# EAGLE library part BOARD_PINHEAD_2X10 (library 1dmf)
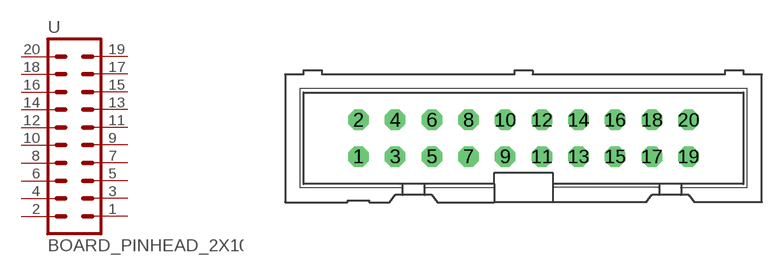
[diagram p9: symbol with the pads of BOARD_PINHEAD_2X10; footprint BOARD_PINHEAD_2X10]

Designator prefix -

## BOARD_PINHEAD_2X10  [BOARD_PINHEAD_2X10]
1  1  pas
2  2  pas
3  3  pas
4  4  pas
5  5  pas
6  6  pas
7  7  pas
8  8  pas
9  9  pas
10  10  pas
11  11  pas
12  12  pas
13  13  pas
14  14  pas
15  15  pas
16  16  pas
17  17  pas
18  18  pas
19  19  pas
20  20  pas

## Footprint BOARD_PINHEAD_2X10 (pad centres in mm)
drill 0.914 octagon: 1 -11.43,-1.27; 2 -11.43,1.27; 3 -8.89,-1.27; 4 -8.89,1.27; 5 -6.35,-1.27; 6 -6.35,1.27; 7 -3.81,-1.27; 8 -3.81,1.27; 9 -1.27,-1.27; 10 -1.27,1.27; 11 1.27,-1.27; 12 1.27,1.27; 13 3.81,-1.27; 14 3.81,1.27; 15 6.35,-1.27; 16 6.35,1.27; 17 8.89,-1.27; 18 8.89,1.27; 19 11.43,-1.27; 20 11.43,1.27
